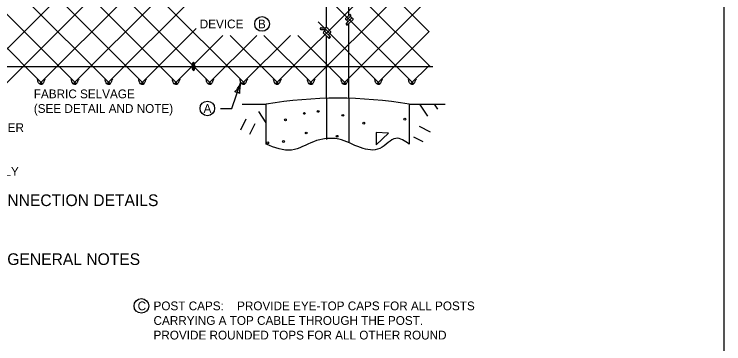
# Model space of a CAD drawing. Extents: x 49973.1 to 50021, y 49987.6 to 50015.4.
# Drawn here: x 50011.891 to 50016.75, y 49993.508 to 49995.764 of the extents above; entities that cross this region are included whole.
import ezdxf

# ---------------------------------------------------------------- set-up
doc = ezdxf.new("R2010")
doc.units = 0
for name, color, linetype in [('Level 1', 7, 'Continuous'), ('Level 2', 7, 'Continuous'), ('Level 3', 7, 'Continuous'), ('Level 4', 7, 'Continuous')]:
    doc.layers.add(name, color=color, linetype=linetype)

msp = doc.modelspace()

# ---------------------------------------------------------------- linework, layer by layer
at = {"layer": 'Level 1'}
for p, q in [((50010.69, 49997.8389), (50013.2411, 49995.2878)), ((50010.9209, 49997.8389), (50013.4721, 49995.2878)), ((50011.6028, 49995.2873), (50014.1545, 49997.8389)), ((50012.0648, 49995.2872), (50014.6165, 49997.8389)), ((50012.0756, 49997.8389), (50014.6268, 49995.2878)), ((50012.3066, 49997.8389), (50014.7388, 49995.4066)), ((50012.5375, 49997.8389), (50014.732, 49995.6444)), ((50010.5445, 49997.7534), (50013.0102, 49995.2878)), ((50012.2958, 49995.2872), (50014.732, 49997.7234)), ((50010.5445, 49997.5225), (50012.7792, 49995.2878)), ((50011.8338, 49995.2872), (50014.0789, 49997.5324)), ((50010.5445, 49997.2915), (50012.5482, 49995.2878)), ((50010.5445, 49997.0606), (50012.3172, 49995.2879)), ((50010.5445, 49996.8297), (50012.0863, 49995.2879)), ((50013.6811, 49995.2867), (50014.732, 49996.3375)), ((50013.9121, 49995.2867), (50014.732, 49996.1066)), ((50012.5267, 49995.2871), (50013.1367, 49995.8971)), ((50014.0301, 49995.6706), (50014.0301, 49995.8782)), ((50014.1434, 49995.2871), (50014.732, 49995.8757)), ((50014.1831, 49995.7583), (50014.1831, 49995.8782)), ((50014.1865, 49995.761), (50014.1598, 49995.7345)), ((50014.1975, 49995.7527), (50014.1701, 49995.7252)), ((50013.9726, 49995.711), (50014.3958, 49995.2878)), ((50014.201, 49995.7368), (50014.164, 49995.7)), ((50014.2117, 49995.7279), (50014.1744, 49995.6909)), ((50012.7577, 49995.2871), (50013.1367, 49995.6661)), ((50013.9934, 49995.6716), (50014.0232, 49995.6716)), ((50014.0232, 49995.6578), (50013.9935, 49995.6578)), ((50014.0295, 49995.6555), (50014.0499, 49995.6351)), ((50014.0379, 49995.6662), (50014.0602, 49995.6444)), ((50014.1831, 49995.6794), (50014.1831, 49995.6995)), ((50014.1831, 49995.3449), (50014.1831, 49995.6794)), ((50012.9887, 49995.2871), (50013.3211, 49995.6194)), ((50013.2196, 49995.2871), (50013.552, 49995.6194)), ((50013.3706, 49995.6194), (50013.7026, 49995.2874)), ((50013.4506, 49995.2871), (50013.7829, 49995.6194)), ((50013.6015, 49995.6194), (50013.9336, 49995.2874)), ((50013.8332, 49995.6194), (50014.1649, 49995.2878)), ((50014.008, 49995.6378), (50014.0453, 49995.601)), ((50014.0191, 49995.6466), (50014.0561, 49995.6098)), ((50014.0301, 49995.3449), (50014.0301, 49995.616)), ((50014.3743, 49995.2871), (50014.732, 49995.6447)), ((50014.6053, 49995.2871), (50014.732, 49995.4138)), ((50011.7524, 49995.4066), (50012.926, 49995.4066)), ((50012.9038, 49995.4066), (50013.0536, 49995.4066)), ((50013.0536, 49995.4066), (50013.1223, 49995.4066)), ((50013.1296, 49995.4066), (50014.7581, 49995.4066)), ((50014.0301, 49995.1882), (50014.0301, 49995.3449)), ((50014.1831, 49995.1882), (50014.1831, 49995.3449)), ((50013.4535, 49995.1483), (50013.6167, 49995.1483)), ((50013.6167, 49994.8748), (50013.6167, 49995.1483)), ((50014.5966, 49995.1483), (50014.8416, 49995.1483)), ((50014.5966, 49995.1483), (50014.5966, 49994.8748)), ((50014.7225, 49995.0671), (50014.6699, 49995.1483)), ((50014.7925, 49995.1134), (50014.7697, 49995.1483)), ((50013.6167, 49995.0202), (50013.566, 49995.0985)), ((50013.4441, 49994.9738), (50013.4809, 49995.0475)), ((50013.5045, 49994.942), (50013.5421, 49995.0171)), ((50014.7416, 49994.9559), (50014.667, 49994.995)), ((50014.3695, 49994.9554), (50014.3695, 49994.8705)), ((50014.4545, 49994.951), (50014.3695, 49994.9554)), ((50014.3695, 49994.8705), (50014.4545, 49994.951)), ((50014.6919, 49994.8905), (50014.6286, 49994.9236))]:
    msp.add_line(p, q, dxfattribs=at)
msp.add_lwpolyline([(49999.3835, 49998.9992), (50016.7501, 49998.9992), (50016.7501, 49987.7988), (49999.3835, 49987.7988)], close=True, dxfattribs=at)
for centre in [(50013.8781, 49995.0854), (50013.9722, 49995.0988), (50014.1422, 49995.0719), (50013.7483, 49995.0406), (50014.2845, 49995.0183), (50014.5665, 49995.0452), (50013.8915, 49994.9511), (50014.102, 49994.9287), (50013.6274, 49994.8841), (50013.7349, 49994.8929)]:
    msp.add_circle(centre, 0.00629, dxfattribs=at)
for centre, radius, start, end in [((50014.1902, 49995.7545), 0.00751, 345.8244, 119.6429), ((50014.1675, 49995.7328), 0.00795, 166.9847, 288.6576), ((50014.178, 49995.7233), 0.00814, 166.2488, 279.4659), ((50014.1937, 49995.7386), 0.00754, 345.4637, 117.6159), ((50014.2044, 49995.7299), 0.00762, 344.6345, 116.7867), ((50013.9934, 49995.6647), 0.00689, 90, 270.0144), ((50014.0263, 49995.6487), 0.00751, 64.5622, 196.7144), ((50014.0237, 49995.6503), 0.0213, 46.4857, 91.3167), ((50014.0235, 49995.649), 0.00881, 47.3268, 92.1578), ((50014.1717, 49995.6983), 0.00795, 167.9722, 289.6451), ((50014.1666, 49995.6925), 0.00795, 347.9722, 109.6451), ((50014.0155, 49995.6397), 0.00773, 62.4072, 194.5594), ((50014.0425, 49995.6327), 0.00778, 255.7403, 17.4131), ((50014.0531, 49995.6024), 0.00798, 68.453, 190.1258), ((50014.0482, 49995.6084), 0.00798, 248.453, 10.1258), ((50014.0525, 49995.6426), 0.00795, 251.3012, 12.974), ((50014.1066, 49992.2381), 2.9511, 80.4434, 99.5566)]:
    msp.add_arc(centre, radius, start, end, dxfattribs=at)
for centre, major_axis, ratio, start_param, end_param in [((50013.1189, 49995.4066), (0.0004, -0.0279), 0.383232, 4.86378, 10.729979), ((50013.112, 49995.4129), (-0.00355, 0.00095), 0.282483, 0.154702, 3.14159), ((50013.1189, 49995.4066), (0.0003, -0.0206), 0.163161, 4.86378, 10.729979)]:
    msp.add_ellipse(centre, major_axis=major_axis, ratio=ratio, start_param=start_param, end_param=end_param, dxfattribs=at)
msp.add_ellipse((50013.112, 49995.4029), major_axis=(-0.00362, -0.0006), ratio=0.282483, dxfattribs=at)
for points in [[(50012.0759, 49995.2983), (50012.0808, 49995.2926), (50012.0789, 49995.2871), (50012.071, 49995.284), (50012.0587, 49995.2944), (50012.0514, 49995.317)], [(50012.0759, 49995.2983), (50012.0722, 49995.2913), (50012.0752, 49995.2858), (50012.0881, 49995.2901), (50012.0973, 49995.3066), (50012.1046, 49995.3219)], [(50012.3069, 49995.2983), (50012.3117, 49995.2925), (50012.3099, 49995.287), (50012.3019, 49995.284), (50012.2897, 49995.2944), (50012.2824, 49995.317)], [(50012.3069, 49995.2983), (50012.3032, 49995.2913), (50012.3062, 49995.2858), (50012.3191, 49995.2901), (50012.3282, 49995.3066), (50012.3356, 49995.3219)], [(50012.5378, 49995.2982), (50012.5427, 49995.2925), (50012.5409, 49995.287), (50012.5329, 49995.2839), (50012.5207, 49995.2943), (50012.5133, 49995.3169)], [(50012.5378, 49995.2982), (50012.5341, 49995.2913), (50012.5372, 49995.2858), (50012.55, 49995.2901), (50012.5592, 49995.3066), (50012.5666, 49995.3218)], [(50012.7688, 49995.2982), (50012.7737, 49995.2925), (50012.7718, 49995.287), (50012.7639, 49995.2839), (50012.7517, 49995.2943), (50012.7443, 49995.3169)], [(50012.7688, 49995.2982), (50012.7651, 49995.2912), (50012.7682, 49995.2857), (50012.781, 49995.29), (50012.7902, 49995.3065), (50012.7975, 49995.3218)], [(50012.9998, 49995.2982), (50013.0047, 49995.2924), (50013.0028, 49995.2869), (50012.9949, 49995.2839), (50012.9826, 49995.2943), (50012.9753, 49995.3169)], [(50012.9998, 49995.2982), (50012.9961, 49995.2912), (50012.9992, 49995.2857), (50013.012, 49995.29), (50013.0212, 49995.3065), (50013.0285, 49995.3218)], [(50013.2307, 49995.2982), (50013.2356, 49995.2924), (50013.2338, 49995.2869), (50013.2258, 49995.2839), (50013.2136, 49995.2943), (50013.2062, 49995.3169)], [(50013.2307, 49995.2982), (50013.227, 49995.2912), (50013.2301, 49995.2857), (50013.2429, 49995.29), (50013.2521, 49995.3065), (50013.2594, 49995.3218)], [(50013.4617, 49995.2982), (50013.4665, 49995.2924), (50013.4647, 49995.2869), (50013.4568, 49995.2839), (50013.4445, 49995.2943), (50013.4372, 49995.3169)], [(50013.4617, 49995.2982), (50013.458, 49995.2912), (50013.461, 49995.2857), (50013.4739, 49995.29), (50013.4831, 49995.3065), (50013.4904, 49995.3218)], [(50013.6922, 49995.2978), (50013.6971, 49995.2921), (50013.6953, 49995.2866), (50013.6873, 49995.2835), (50013.6751, 49995.2939), (50013.6678, 49995.3165)], [(50013.6922, 49995.2978), (50013.6885, 49995.2908), (50013.6916, 49995.2853), (50013.7044, 49995.2896), (50013.7136, 49995.3061), (50013.721, 49995.3214)], [(50013.9232, 49995.2978), (50013.928, 49995.2921), (50013.9262, 49995.2866), (50013.9183, 49995.2835), (50013.906, 49995.2939), (50013.8987, 49995.3165)], [(50013.9232, 49995.2978), (50013.9195, 49995.2908), (50013.9225, 49995.2853), (50013.9354, 49995.2896), (50013.9446, 49995.3061), (50013.9519, 49995.3214)], [(50014.1545, 49995.2982), (50014.1594, 49995.2924), (50014.1575, 49995.2869), (50014.1496, 49995.2839), (50014.1373, 49995.2943), (50014.13, 49995.3169)], [(50014.1545, 49995.2982), (50014.1508, 49995.2912), (50014.1539, 49995.2857), (50014.1667, 49995.29), (50014.1759, 49995.3065), (50014.1832, 49995.3218)], [(50014.3854, 49995.2982), (50014.3903, 49995.2924), (50014.3885, 49995.2869), (50014.3805, 49995.2839), (50014.3683, 49995.2943), (50014.3609, 49995.3169)], [(50014.3854, 49995.2982), (50014.3817, 49995.2912), (50014.3848, 49995.2857), (50014.3976, 49995.29), (50014.4068, 49995.3065), (50014.4142, 49995.3218)], [(50014.6164, 49995.2982), (50014.6212, 49995.2924), (50014.6194, 49995.2869), (50014.6115, 49995.2839), (50014.5992, 49995.2943), (50014.5919, 49995.3169)], [(50014.6164, 49995.2982), (50014.6127, 49995.2912), (50014.6157, 49995.2857), (50014.6286, 49995.29), (50014.6378, 49995.3065), (50014.6451, 49995.3218)], [(50014.5966, 49994.8748), (50014.5051, 49994.9145), (50014.3957, 49994.8453), (50014.2632, 49994.8511), (50014.1135, 49994.9087), (50013.9408, 49994.8914), (50013.7911, 49994.8338), (50013.6167, 49994.8748)]]:
    msp.add_spline(points, degree=3, dxfattribs=at)
at = {"layer": 'Level 2'}
for centre in [(50013.5884, 49995.6974), (50013.2139, 49995.1188), (50012.7624, 49993.7675)]:
    msp.add_circle(centre, 0.05, dxfattribs=at)
at = {"layer": 'Level 3'}
for p, q in [((50013.381, 49995.1188), (50013.4433, 49995.298)), ((50013.3039, 49995.1188), (50013.381, 49995.1188))]:
    msp.add_line(p, q, dxfattribs=at)
for centre, radius, start, end in [((50013.2365, 49995.3796), 0.2223, 318.2759, 338.4594), ((50013.6669, 49995.2324), 0.233, 163.6472, 182.8971), ((50013.4012, 49995.1769), 0.0548, 52.9587, 88.6811)]:
    msp.add_arc(centre, radius, start, end, dxfattribs=at)
at = {"layer": 'Level 4'}
for p, q in [((50014.0301, 49995.1882), (50014.0301, 49994.9071)), ((50014.1831, 49995.1882), (50014.1831, 49994.8841))]:
    msp.add_line(p, q, dxfattribs=at)

# ---------------------------------------------------------------- texts
at = {"layer": 'Level 2'}
for s, height, p in [('DEVICE', 0.06, (50013.1618, 49995.6674)), ('B', 0.06, (50013.5606, 49995.6674)), ('FABRIC SELVAGE', 0.06, (50012.0258, 49995.1888)), ('(SEE DETAIL AND NOTE)', 0.06, (50012.0258, 49995.0888)), ('A', 0.06, (50013.1881, 49995.0888)), ('RING FASTENER', 0.06, (50011.3077, 49994.9579)), ('HORIZONTALLY', 0.06, (50011.3077, 49994.6579)), ('CONNECTION DETAILS', 0.08, (50011.6841, 49994.4507)), ('GENERAL NOTES', 0.08, (50011.8441, 49994.0475)), ('C', 0.06, (50012.7368, 49993.7375)), ('POST CAPS:', 0.06, (50012.8455, 49993.7375)), ('  PROVIDE EYE-TOP CAPS FOR ALL POSTS', 0.06, (50013.373, 49993.7375)), ('CARRYING A TOP CABLE THROUGH THE POST. ', 0.06, (50012.8455, 49993.6375)), ('PROVIDE ROUNDED TOPS FOR ALL OTHER ROUND', 0.06, (50012.8455, 49993.5375))]:
    msp.add_text(s, height=height, dxfattribs=at).set_placement(p)

doc.saveas('drawing.dxf')
